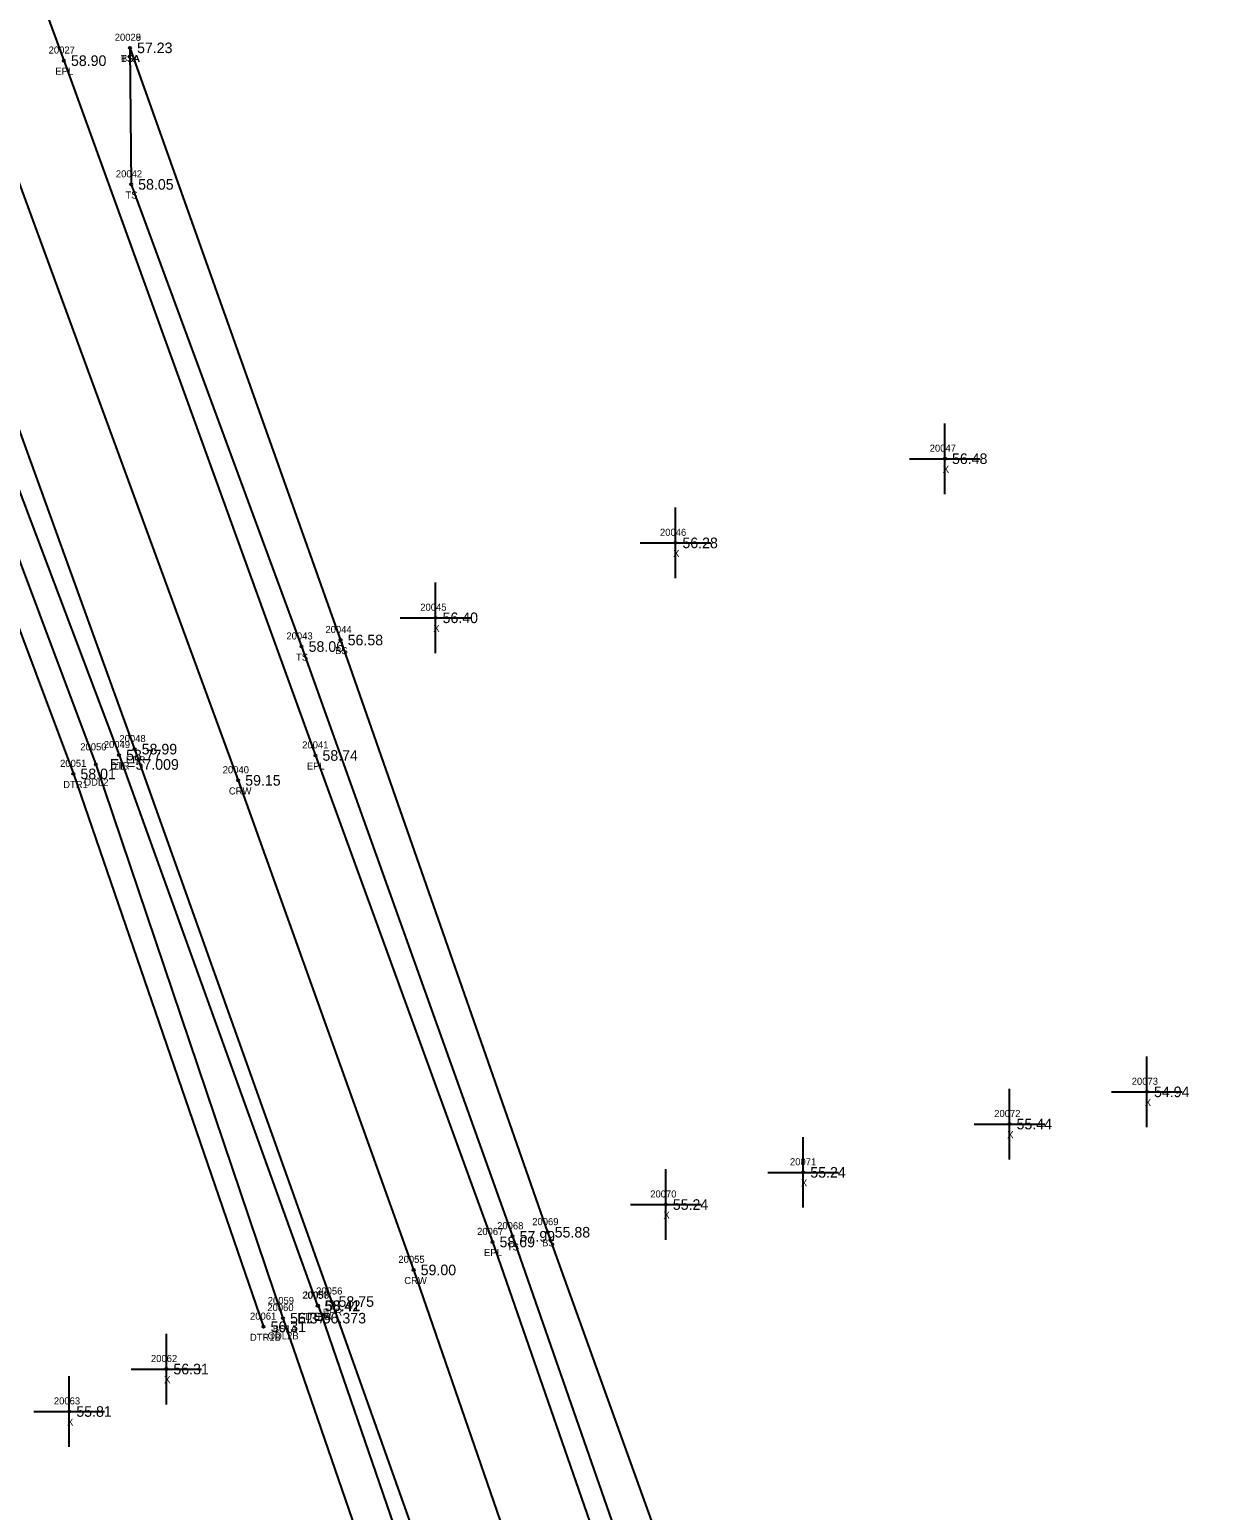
# Model space of a CAD drawing. Extents: x 2396547 to 2397655, y 770185 to 772649.
# Drawn here: x 2396745.8 to 2396913.2, y 772225.3 to 772435 of the extents above; entities that cross this region are included whole.
import ezdxf

# ---------------------------------------------------------------- set-up
doc = ezdxf.new("R2010")
doc.units = 0
for name, color, linetype in [('RD_DTM_BkLn1', 7, 'Continuous'), ('RD_DTM_BkLn2', 7, 'Continuous'), ('RD_DTM_BkLn_txCode', 7, 'Continuous'), ('RD_EX_H2O', 7, 'Continuous'), ('RD_EX_H2O_txCode', 7, 'Continuous'), ('RD_EX_Misc', 7, 'Continuous'), ('RD_EX_Misc_txCode', 7, 'Continuous'), ('RD_EX_Road', 7, 'Continuous'), ('RD_EX_Road_txCode', 7, 'Continuous'), ('RD_EX_TX_H2O_ELEV', 7, 'Continuous'), ('RD_EX_TX_Misc_ELEV', 7, 'Continuous'), ('RD_EX_TX_Road_ELEV', 7, 'Continuous'), ('RD_HC_Survey_ELEV', 7, 'Continuous'), ('RD_HC_Survey_txCode', 7, 'Continuous'), ('RD_SMD_Locator', 7, 'Continuous')]:
    doc.layers.add(name, color=color, linetype=linetype)

msp = doc.modelspace()

# ---------------------------------------------------------------- linework, layer by layer
at = {"layer": 'RD_DTM_BkLn1'}
msp.add_lwpolyline([(2396669.86, 772614.94), (2396704.28, 772521.49), (2396739.29, 772426.89), (2396775.36, 772328.69), (2396800.21, 772259.35), (2396825.58, 772185.8), (2396852.46, 772104.52), (2396872.48, 772041.55), (2396897.57, 771959.72), (2396918.76, 771888.68), (2396939.09, 771818.34), (2396959.29, 771747.62), (2396993.72, 771617.68), (2397022.56, 771506.67), (2397049.1, 771404.69)], dxfattribs=at)
at = {"layer": 'RD_DTM_BkLn2'}
for points in [[(2396760.04, 772432.43), (2396789.87, 772348.56), (2396819.19, 772264.69), (2396848.46, 772183.36), (2396871.43, 772111.95), (2396893.38, 772049.37), (2396898.43, 772032.73), (2396909.27, 772037.73)], [(2396760.04, 772432.43), (2396760.2, 772413.09), (2396784.34, 772347.64), (2396814.22, 772264.11), (2396842.68, 772182.48), (2396866.31, 772110.61), (2396887.53, 772047.36), (2396893.79, 772029.88), (2396898.47, 772029.01), (2396909.27, 772037.73)], [(2396786.67, 772254.3), (2396812.18, 772180.2), (2396838.8, 772099.9), (2396858.54, 772037.17), (2396883.18, 771955.21), (2396904.21, 771884.05), (2396902.37, 771874.08)], [(2396781.71, 772252.52), (2396807.28, 772178.23), (2396832.42, 772097.31), (2396850.69, 772038.97), (2396852.44, 772035.31), (2396852.26, 772031.59), (2396879.38, 771953.92), (2396900.31, 771883.04), (2396902.37, 771874.08)]]:
    msp.add_lwpolyline(points, dxfattribs=at)
at = {"layer": 'RD_EX_H2O'}
for points in [[(2396654.89, 772610.44), (2396689.53, 772515.4), (2396726.4, 772417.15), (2396758.49, 772332.26), (2396786.59, 772254.26)], [(2396652.28, 772609.21), (2396687.19, 772514.46), (2396723.26, 772416.1), (2396755.2, 772330.94), (2396781.71, 772252.52)], [(2396647.52, 772607.47), (2396683.51, 772512.21), (2396720.14, 772414.69), (2396752.02, 772329.6), (2396778.94, 772251.31)]]:
    msp.add_lwpolyline(points, dxfattribs=at)
at = {"layer": 'RD_EX_Misc'}
for p, q in [((2396875.46, 772369.24), (2396875.46, 772379.24)), ((2396870.46, 772374.24), (2396880.46, 772374.24)), ((2396837.28, 772357.32), (2396837.28, 772367.32)), ((2396832.28, 772362.32), (2396842.28, 772362.32)), ((2396803.31, 772346.71), (2396803.31, 772356.71)), ((2396798.31, 772351.71), (2396808.31, 772351.71)), ((2396904.07, 772279.57), (2396904.07, 772289.57)), ((2396884.6, 772275.01), (2396884.6, 772285.01)), ((2396899.07, 772284.57), (2396909.07, 772284.57)), ((2396879.6, 772280.01), (2396889.6, 772280.01)), ((2396855.39, 772268.17), (2396855.39, 772278.17)), ((2396835.92, 772263.61), (2396835.92, 772273.61)), ((2396850.39, 772273.17), (2396860.39, 772273.17)), ((2396830.92, 772268.61), (2396840.92, 772268.61)), ((2396765.19, 772240.31), (2396765.19, 772250.31)), ((2396760.19, 772245.31), (2396770.19, 772245.31)), ((2396751.44, 772234.3), (2396751.44, 772244.3)), ((2396746.44, 772239.3), (2396756.44, 772239.3))]:
    msp.add_line(p, q, dxfattribs=at)
at = {"layer": 'RD_EX_Road'}
for points in [[(2396680.92, 772617.84), (2396715.6, 772525.73), (2396750.68, 772430.62), (2396786.3, 772332.21), (2396811.38, 772263.31), (2396839.69, 772181.74), (2396863.75, 772109.83), (2396883.63, 772046.56), (2396889.54, 772027.11), (2396896.25, 772004.37), (2396904.34, 771978.33), (2396908.24, 771964.89), (2396921.74, 771919.68), (2396927.03, 771902.11), (2396950.2, 771821.74), (2396970.47, 771750.68), (2396978.33, 771721.29), (2396990.58, 771675.04), (2397004.94, 771620.49), (2397034.26, 771508.8), (2397061.11, 771410.49), (2397060.64, 771407.04), (2397062.07, 771407.67)], [(2396658.78, 772611.07), (2396693.37, 772516.9), (2396729.65, 772418.78), (2396760.7, 772333.11), (2396788.58, 772254.87), (2396814.65, 772181.57), (2396841.1, 772100.86), (2396861.19, 772037.76), (2396886.09, 771955.71), (2396907.15, 771884.49), (2396928.56, 771811.72), (2396947.65, 771744.09), (2396985.17, 771602.64), (2397011.11, 771504.04), (2397037.95, 771404.25), (2397039, 771401.22)]]:
    msp.add_lwpolyline(points, dxfattribs=at)
at = {"layer": 'RD_SMD_Locator'}
for centre in [(2396760.04, 772432.43), (2396760.04, 772432.43), (2396750.68, 772430.62), (2396760.2, 772413.09), (2396875.46, 772374.24), (2396837.28, 772362.32), (2396803.31, 772351.71), (2396784.34, 772347.64), (2396789.87, 772348.56), (2396760.7, 772333.11), (2396755.2, 772330.94), (2396758.49, 772332.26), (2396786.3, 772332.21), (2396752.02, 772329.6), (2396775.36, 772328.69), (2396904.07, 772284.57), (2396884.6, 772280.01), (2396855.39, 772273.17), (2396835.92, 772268.61), (2396814.22, 772264.11), (2396819.19, 772264.69), (2396811.38, 772263.31), (2396800.21, 772259.35), (2396786.59, 772254.26), (2396786.67, 772254.3), (2396788.58, 772254.87), (2396778.94, 772251.31), (2396781.71, 772252.52), (2396781.71, 772252.52), (2396765.19, 772245.31), (2396751.44, 772239.3)]:
    msp.add_circle(centre, 0.15, dxfattribs=at)

# ---------------------------------------------------------------- texts
at = {"layer": 'RD_DTM_BkLn_txCode'}
for s, p in [('20028', (2396757.88, 772433.43)), ('20029', (2396757.88, 772433.43)), ('TSA', (2396758.76, 772430.43)), ('BSA', (2396758.77, 772430.43)), ('20042', (2396758.04, 772414.09)), ('TS', (2396759.4, 772411.09)), ('20044', (2396787.72, 772349.56)), ('20043', (2396782.19, 772348.64)), ('TS', (2396783.55, 772345.64)), ('BS', (2396789.1, 772346.56)), ('20068', (2396812.04, 772265.11)), ('20069', (2396817.01, 772265.69)), ('TS', (2396813.43, 772262.11)), ('BS', (2396818.41, 772262.69)), ('20058', (2396784.51, 772255.3)), ('20060', (2396779.49, 772253.52)), ('BS1A', (2396780.27, 772250.52)), ('TS1A', (2396785.22, 772252.3))]:
    msp.add_text(s, height=1, dxfattribs=at).set_placement(p)
at = {"layer": 'RD_EX_H2O_txCode'}
for s, p in [('20050', (2396753, 772332.94)), ('20049', (2396756.33, 772333.26)), ('20051', (2396750.14, 772330.6)), ('DTR', (2396757.22, 772330.26)), ('ODL2', (2396753.5, 772327.94)), ('DTR1', (2396750.58, 772327.6)), ('20059', (2396779.55, 772254.52)), ('20057', (2396784.44, 772255.26)), ('20061', (2396777.04, 772252.31)), ('DTRB', (2396784.85, 772252.26)), ('DTR1B', (2396777.03, 772249.31)), ('ODL2B', (2396779.54, 772249.52))]:
    msp.add_text(s, height=1, dxfattribs=at).set_placement(p)
at = {"layer": 'RD_EX_Misc_txCode'}
for s, p in [('20047', (2396873.3, 772375.24)), ('X', (2396875.15, 772372.24)), ('20046', (2396835.1, 772363.32)), ('X', (2396836.96, 772360.32)), ('20045', (2396801.15, 772352.71)), ('X', (2396803, 772349.71)), ('20073', (2396901.91, 772285.57)), ('X', (2396903.76, 772282.57)), ('20072', (2396882.44, 772281.01)), ('X', (2396884.28, 772278.01)), ('20071', (2396853.51, 772274.17)), ('20070', (2396833.72, 772269.61)), ('X', (2396855.07, 772271.17)), ('X', (2396835.6, 772266.61)), ('20062', (2396763.01, 772246.31)), ('X', (2396764.88, 772243.31)), ('20063', (2396749.26, 772240.3)), ('X', (2396751.13, 772237.3))]:
    msp.add_text(s, height=1, dxfattribs=at).set_placement(p)
at = {"layer": 'RD_EX_Road_txCode'}
for s, p in [('20027', (2396748.52, 772431.62)), ('EPL', (2396749.47, 772428.62)), ('20048', (2396758.54, 772334.11)), ('20041', (2396784.43, 772333.21)), ('EPR', (2396759.47, 772331.11)), ('EPL', (2396785.09, 772330.21)), ('20067', (2396809.2, 772264.31)), ('EPL', (2396810.18, 772261.31)), ('20056', (2396786.4, 772255.87)), ('EPR', (2396787.35, 772252.87))]:
    msp.add_text(s, height=1, dxfattribs=at).set_placement(p)
at = {"layer": 'RD_EX_TX_H2O_ELEV'}
for s, p in [('EL=57.009', (2396757.2, 772330.19)), ('58.77', (2396759.49, 772331.51)), ('58.01', (2396753.02, 772328.85)), ('58.41', (2396787.59, 772253.51)), ('56.31', (2396779.94, 772250.56)), ('EL=56.373', (2396783.71, 772251.77))]:
    msp.add_text(s, height=1.5, dxfattribs=at).set_placement(p)
at = {"layer": 'RD_EX_TX_Misc_ELEV'}
for s, p in [('57.23', (2396761.04, 772431.68)), ('57.23', (2396761.04, 772431.68)), ('58.05', (2396761.2, 772412.34)), ('56.48', (2396876.46, 772373.49)), ('56.28', (2396838.28, 772361.57)), ('56.40', (2396804.31, 772350.96)), ('58.06', (2396785.34, 772346.89)), ('56.58', (2396790.87, 772347.81)), ('54.94', (2396905.07, 772283.82)), ('55.44', (2396885.6, 772279.26)), ('55.24', (2396856.39, 772272.42)), ('55.24', (2396836.92, 772267.86)), ('57.99', (2396815.22, 772263.36)), ('55.88', (2396820.19, 772263.94)), ('58.42', (2396787.67, 772253.55)), ('56.37', (2396782.71, 772251.77)), ('56.31', (2396766.19, 772244.56)), ('55.81', (2396752.44, 772238.55))]:
    msp.add_text(s, height=1.5, dxfattribs=at).set_placement(p)
at = {"layer": 'RD_EX_TX_Road_ELEV'}
for s, p in [('58.90', (2396751.68, 772429.87)), ('58.99', (2396761.7, 772332.36)), ('58.74', (2396787.3, 772331.46)), ('58.69', (2396812.38, 772262.56)), ('58.75', (2396789.58, 772254.12))]:
    msp.add_text(s, height=1.5, dxfattribs=at).set_placement(p)
at = {"layer": 'RD_HC_Survey_ELEV'}
for s, p in [('59.15', (2396776.36, 772327.94)), ('59.00', (2396801.21, 772258.6))]:
    msp.add_text(s, height=1.5, dxfattribs=at).set_placement(p)
at = {"layer": 'RD_HC_Survey_txCode'}
for s, p in [('20040', (2396773.17, 772329.69)), ('CRW', (2396774.05, 772326.69)), ('20055', (2396798.05, 772260.35)), ('CRW', (2396798.89, 772257.35))]:
    msp.add_text(s, height=1, dxfattribs=at).set_placement(p)

doc.saveas('drawing.dxf')
